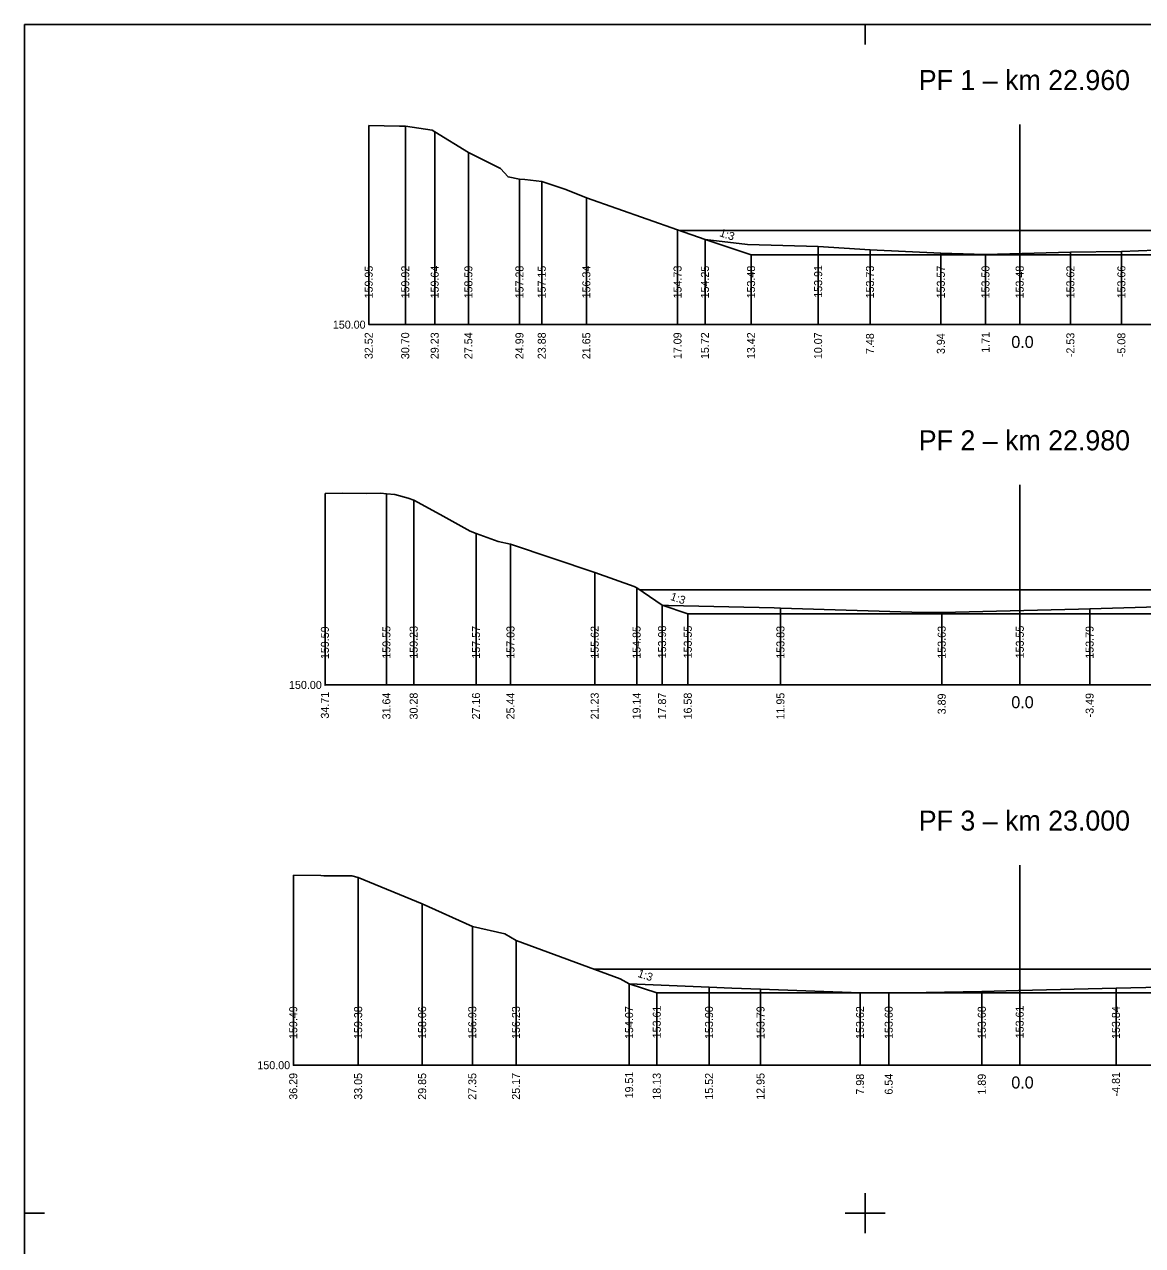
# Model space of a CAD drawing. Extents: x -582678 to -581845, y -1210354 to -1210235.
# Drawn here: x -582677.5 to -582621.6, y -1210296.3 to -1210235.3 of the extents above; entities that cross this region are included whole.
import ezdxf

# ---------------------------------------------------------------- set-up
doc = ezdxf.new("R2010")
doc.units = 0
for name, color, linetype in [('_N_osa', 7, 'Continuous'), ('_N_popis', 7, 'Continuous'), ('_N_tučná', 7, 'Continuous'), ('_rámeček', 7, 'Continuous'), ('_S_hladina', 7, 'Continuous'), ('_S_popis', 7, 'Continuous'), ('_S_popis_oprav!', 7, 'Continuous'), ('_S_tenká', 7, 'Continuous'), ('_S_velmi_tenká', 7, 'Continuous')]:
    doc.layers.add(name, color=color, linetype=linetype)

msp = doc.modelspace()

# ---------------------------------------------------------------- linework, layer by layer
at = {"layer": '_N_osa'}
for p, q in [((-582627.772, -1210240.291), (-582627.772, -1210250.291)), ((-582627.772, -1210258.291), (-582627.772, -1210268.291)), ((-582627.772, -1210277.291), (-582627.772, -1210287.291))]:
    msp.add_line(p, q, dxfattribs=at)
at = {"layer": '_N_popis'}
for points in [[(-582643.497, -1210246.043), (-582643.497, -1210250.291), (-582643.497, -1210250.291), (-582643.497, -1210250.291)], [(-582641.192, -1210246.811), (-582641.192, -1210250.291), (-582641.192, -1210250.291), (-582641.192, -1210250.291)], [(-582645.637, -1210264.313), (-582645.637, -1210268.291), (-582645.637, -1210268.291), (-582645.637, -1210268.291)], [(-582644.354, -1210264.741), (-582644.354, -1210268.291), (-582644.354, -1210268.291), (-582644.354, -1210268.291)], [(-582647.284, -1210283.221), (-582647.284, -1210287.291), (-582647.284, -1210287.291), (-582647.284, -1210287.291)], [(-582645.904, -1210283.681), (-582645.904, -1210287.291), (-582645.904, -1210287.291), (-582645.904, -1210287.291)]]:
    msp.add_lwpolyline(points, dxfattribs=at)
at = {"layer": '_N_tučná'}
for p, q in [((-582643.497, -1210246.043), (-582641.192, -1210246.811)), ((-582606.977, -1210246.811), (-582641.192, -1210246.811)), ((-582645.637, -1210264.313), (-582644.354, -1210264.741)), ((-582647.284, -1210283.221), (-582645.904, -1210283.681))]:
    msp.add_line(p, q, dxfattribs=at)
for points in [[(-582605.815, -1210264.741), (-582644.354, -1210264.741)], [(-582604.941, -1210283.681), (-582645.904, -1210283.681)]]:
    msp.add_lwpolyline(points, dxfattribs=at)
at = {"layer": '_rámeček'}
for p, q in [((-582677.502, -1210235.291), (-582677.502, -1210354.091)), ((-582467.502, -1210235.291), (-582677.502, -1210235.291)), ((-582635.502, -1210235.291), (-582635.502, -1210236.291)), ((-582635.502, -1210293.691), (-582635.502, -1210295.691)), ((-582677.502, -1210294.691), (-582676.502, -1210294.691)), ((-582636.502, -1210294.691), (-582634.502, -1210294.691))]:
    msp.add_line(p, q, dxfattribs=at)
at = {"layer": '_S_hladina'}
for points in [[(-582644.77, -1210245.591), (-582603.296, -1210245.591)], [(-582646.766, -1210263.541), (-582602.321, -1210263.541)], [(-582649.014, -1210282.501), (-582601.439, -1210282.501)]]:
    msp.add_lwpolyline(points, dxfattribs=at)
at = {"layer": '_S_tenká'}
for p, q in [((-582587.316, -1210250.291), (-582660.294, -1210250.291)), ((-582584.418, -1210268.291), (-582662.484, -1210268.291)), ((-582582.203, -1210287.291), (-582664.065, -1210287.291))]:
    msp.add_line(p, q, dxfattribs=at)
for points in [[(-582618.443, -1210246.469), (-582622.691, -1210246.633), (-582625.239, -1210246.67), (-582629.482, -1210246.788), (-582631.711, -1210246.721), (-582635.252, -1210246.559), (-582637.841, -1210246.38), (-582641.383, -1210246.287), (-582643.497, -1210246.043), (-582644.866, -1210245.557), (-582649.424, -1210243.955), (-582650.454, -1210243.546), (-582651.649, -1210243.14), (-582652.497, -1210243.04), (-582652.763, -1210243.016), (-582653.335, -1210242.907), (-582653.723, -1210242.484), (-582654.282, -1210242.199), (-582654.819, -1210241.933), (-582655.315, -1210241.697), (-582656.998, -1210240.655), (-582657.139, -1210240.581), (-582658.471, -1210240.373), (-582658.763, -1210240.373), (-582660.294, -1210240.345)], [(-582618.037, -1210264.313), (-582624.278, -1210264.498), (-582624.833, -1210264.51), (-582631.667, -1210264.665), (-582632.158, -1210264.68), (-582632.612, -1210264.674), (-582639.726, -1210264.461), (-582640.05, -1210264.448), (-582645.317, -1210264.328), (-582645.637, -1210264.313), (-582646.912, -1210263.441), (-582647.038, -1210263.37), (-582649.005, -1210262.676), (-582653.211, -1210261.258), (-582653.826, -1210261.133), (-582654.934, -1210260.722), (-582655.225, -1210260.61), (-582656.73, -1210259.779), (-582658.05, -1210259.064), (-582658.336, -1210258.954), (-582659.002, -1210258.772), (-582659.411, -1210258.741), (-582659.694, -1210258.719), (-582660.421, -1210258.734), (-582661.623, -1210258.705), (-582662.484, -1210258.726)], [(-582620.747, -1210283.397), (-582622.964, -1210283.447), (-582627.835, -1210283.554), (-582629.664, -1210283.611), (-582634.315, -1210283.692), (-582635.749, -1210283.675), (-582640.72, -1210283.497), (-582642.166, -1210283.44), (-582643.291, -1210283.386), (-582647.284, -1210283.221), (-582647.733, -1210282.97), (-582652.938, -1210281.065), (-582653.503, -1210280.731), (-582655.121, -1210280.357), (-582657.625, -1210279.228), (-582660.822, -1210277.909), (-582661.149, -1210277.838), (-582661.993, -1210277.829), (-582662.55, -1210277.823), (-582662.701, -1210277.821), (-582664.065, -1210277.803)]]:
    msp.add_lwpolyline(points, dxfattribs=at)
at = {"layer": '_S_velmi_tenká'}
for points in [[(-582660.294, -1210240.345), (-582660.294, -1210250.291), (-582660.294, -1210250.291), (-582660.294, -1210250.291)], [(-582658.471, -1210240.373), (-582658.471, -1210250.291), (-582658.471, -1210250.291), (-582658.471, -1210250.291)], [(-582656.998, -1210240.655), (-582656.998, -1210250.291), (-582656.998, -1210250.291), (-582656.998, -1210250.291)], [(-582655.315, -1210241.697), (-582655.315, -1210250.291), (-582655.315, -1210250.291), (-582655.315, -1210250.291)], [(-582652.763, -1210243.016), (-582652.763, -1210250.291), (-582652.763, -1210250.291), (-582652.763, -1210250.291)], [(-582651.649, -1210243.14), (-582651.649, -1210250.291), (-582651.649, -1210250.291), (-582651.649, -1210250.291)], [(-582649.424, -1210243.955), (-582649.424, -1210250.291), (-582649.424, -1210250.291), (-582649.424, -1210250.291)], [(-582644.866, -1210245.557), (-582644.866, -1210250.291), (-582644.866, -1210250.291), (-582644.866, -1210250.291)], [(-582637.841, -1210246.38), (-582637.841, -1210250.291), (-582637.841, -1210250.291), (-582637.841, -1210250.291)], [(-582635.252, -1210246.559), (-582635.252, -1210250.291), (-582635.252, -1210250.291), (-582635.252, -1210250.291)], [(-582625.239, -1210246.67), (-582625.239, -1210250.291), (-582625.239, -1210250.291), (-582625.239, -1210250.291)], [(-582622.691, -1210246.633), (-582622.691, -1210250.291), (-582622.691, -1210250.291), (-582622.691, -1210250.291)], [(-582631.711, -1210246.721), (-582631.711, -1210250.291), (-582631.711, -1210250.291), (-582631.711, -1210250.291)], [(-582629.482, -1210246.788), (-582629.482, -1210250.291), (-582629.482, -1210250.291), (-582629.482, -1210250.291)], [(-582662.484, -1210258.726), (-582662.484, -1210268.312), (-582662.484, -1210268.312), (-582662.484, -1210268.312)], [(-582659.411, -1210258.741), (-582659.411, -1210268.291), (-582659.411, -1210268.291), (-582659.411, -1210268.291)], [(-582658.05, -1210259.064), (-582658.05, -1210268.291), (-582658.05, -1210268.291), (-582658.05, -1210268.291)], [(-582654.934, -1210260.722), (-582654.934, -1210268.291), (-582654.934, -1210268.291), (-582654.934, -1210268.291)], [(-582653.211, -1210261.258), (-582653.211, -1210268.291), (-582653.211, -1210268.291), (-582653.211, -1210268.291)], [(-582649.005, -1210262.676), (-582649.005, -1210268.291), (-582649.005, -1210268.291), (-582649.005, -1210268.291)], [(-582646.912, -1210263.441), (-582646.912, -1210268.291), (-582646.912, -1210268.291), (-582646.912, -1210268.291)], [(-582639.726, -1210264.461), (-582639.726, -1210268.291), (-582639.726, -1210268.291), (-582639.726, -1210268.291)], [(-582631.667, -1210264.665), (-582631.667, -1210268.291), (-582631.667, -1210268.291), (-582631.667, -1210268.291)], [(-582624.278, -1210264.498), (-582624.278, -1210268.291), (-582624.278, -1210268.291), (-582624.278, -1210268.291)], [(-582664.065, -1210277.803), (-582664.065, -1210287.291), (-582664.065, -1210287.291), (-582664.065, -1210287.291)], [(-582660.822, -1210277.909), (-582660.822, -1210287.291), (-582660.822, -1210287.291), (-582660.822, -1210287.291)], [(-582657.625, -1210279.228), (-582657.625, -1210287.291), (-582657.625, -1210287.291), (-582657.625, -1210287.291)], [(-582655.121, -1210280.357), (-582655.121, -1210287.291), (-582655.121, -1210287.291), (-582655.121, -1210287.291)], [(-582652.938, -1210281.065), (-582652.938, -1210287.291), (-582652.938, -1210287.291), (-582652.938, -1210287.291)], [(-582643.291, -1210283.386), (-582643.291, -1210287.291), (-582643.291, -1210287.291), (-582643.291, -1210287.291)], [(-582640.72, -1210283.497), (-582640.72, -1210287.291), (-582640.72, -1210287.291), (-582640.72, -1210287.291)], [(-582635.749, -1210283.675), (-582635.749, -1210287.291), (-582635.749, -1210287.291), (-582635.749, -1210287.291)], [(-582634.315, -1210283.692), (-582634.315, -1210287.291), (-582634.315, -1210287.291), (-582634.315, -1210287.291)], [(-582629.664, -1210283.611), (-582629.664, -1210287.291), (-582629.664, -1210287.291), (-582629.664, -1210287.291)], [(-582622.964, -1210283.447), (-582622.964, -1210287.291), (-582622.964, -1210287.291), (-582622.964, -1210287.291)]]:
    msp.add_lwpolyline(points, dxfattribs=at)

# ---------------------------------------------------------------- texts
at = {"layer": '_N_popis'}
for s, height, rotation, p in [('1:3', 0.4, 341.56505, (-582642.808, -1210245.861)), ('154.25', 0.4, 90, (-582643.304, -1210248.982)), ('153.48', 0.4, 90, (-582640.999, -1210248.982)), ('153.48', 0.4, 90, (-582627.579, -1210248.982)), ('15.72', 0.4, 90, (-582643.304, -1210252.013)), ('13.42', 0.4, 90, (-582640.999, -1210252.013)), ('0.0', 0.6, 360, (-582628.196, -1210251.456)), ('1:3', 0.4, 341.56505, (-582645.261, -1210264.037)), ('153.98', 0.4, 90, (-582645.444, -1210266.966)), ('153.55', 0.4, 90, (-582644.16, -1210266.967)), ('153.55', 0.4, 90, (-582627.572, -1210266.967)), ('17.87', 0.4, 90, (-582645.444, -1210270.016)), ('16.58', 0.4, 90, (-582644.16, -1210270.017)), ('0.0', 0.6, 360, (-582628.196, -1210269.456)), ('1:3', 0.4, 341.56505, (-582646.894, -1210282.87)), ('154.07', 0.4, 90, (-582647.091, -1210285.981)), ('153.61', 0.4, 90, (-582645.711, -1210285.949)), ('153.61', 0.4, 90, (-582627.579, -1210285.949)), ('19.51', 0.4, 90, (-582647.091, -1210288.953)), ('18.13', 0.4, 90, (-582645.711, -1210289.016)), ('0.0', 0.6, 360, (-582628.196, -1210288.456))]:
    msp.add_text(s, height=height, rotation=rotation, dxfattribs=at).set_placement(p)
at = {"layer": '_S_popis'}
for s, p in [('159.95', (-582660.101, -1210248.982)), ('159.92', (-582658.277, -1210248.98)), ('159.64', (-582656.805, -1210248.981)), ('158.59', (-582655.121, -1210248.982)), ('157.28', (-582652.57, -1210248.982)), ('157.15', (-582651.456, -1210248.982)), ('156.34', (-582649.23, -1210248.981)), ('154.73', (-582644.673, -1210248.981)), ('153.91', (-582637.648, -1210248.949)), ('153.73', (-582635.059, -1210248.981)), ('153.57', (-582631.518, -1210248.981)), ('153.50', (-582629.289, -1210248.981)), ('153.62', (-582625.046, -1210248.98)), ('153.66', (-582622.498, -1210248.981)), ('32.52', (-582660.101, -1210252.013)), ('30.70', (-582658.277, -1210252.015)), ('29.23', (-582656.805, -1210252.016)), ('27.54', (-582655.121, -1210252.015)), ('24.99', (-582652.57, -1210252.017)), ('23.88', (-582651.456, -1210252.017)), ('21.65', (-582649.23, -1210252.019)), ('17.09', (-582644.673, -1210252.017)), ('10.07', (-582637.648, -1210252.016)), ('7.48', (-582635.059, -1210251.762)), ('3.94', (-582631.518, -1210251.76)), ('1.71', (-582629.282, -1210251.698)), ('-2.53', (-582625.046, -1210251.914)), ('-5.08', (-582622.498, -1210251.915)), ('159.59', (-582662.291, -1210267.003)), ('159.55', (-582659.217, -1210266.982)), ('159.23', (-582657.857, -1210266.981)), ('157.57', (-582654.741, -1210266.981)), ('157.03', (-582653.018, -1210266.981)), ('155.62', (-582648.811, -1210266.98)), ('154.85', (-582646.719, -1210266.982)), ('153.83', (-582639.532, -1210266.981)), ('153.63', (-582631.474, -1210266.981)), ('153.79', (-582624.085, -1210266.982)), ('34.71', (-582662.291, -1210269.974)), ('31.64', (-582659.217, -1210270.015)), ('30.28', (-582657.857, -1210270.017)), ('27.16', (-582654.741, -1210270.016)), ('25.44', (-582653.018, -1210270.015)), ('21.23', (-582648.811, -1210270.016)), ('19.14', (-582646.719, -1210270.015)), ('11.95', (-582639.532, -1210270.019)), ('3.89', (-582631.474, -1210269.762)), ('-3.49', (-582624.085, -1210269.915)), ('159.49', (-582663.872, -1210285.982)), ('159.38', (-582660.629, -1210285.982)), ('158.06', (-582657.432, -1210285.981)), ('156.93', (-582654.927, -1210285.981)), ('156.23', (-582652.745, -1210285.981)), ('153.90', (-582643.098, -1210285.981)), ('153.79', (-582640.527, -1210285.982)), ('153.62', (-582635.556, -1210285.98)), ('153.60', (-582634.122, -1210285.981)), ('153.68', (-582629.471, -1210285.982)), ('153.84', (-582622.771, -1210285.981)), ('36.29', (-582663.872, -1210289.017)), ('33.05', (-582660.629, -1210289.019)), ('29.85', (-582657.432, -1210289.019)), ('27.35', (-582654.927, -1210289.019)), ('25.17', (-582652.745, -1210289.016)), ('15.52', (-582643.098, -1210289.013)), ('12.95', (-582640.527, -1210289.019)), ('7.98', (-582635.556, -1210288.762)), ('6.54', (-582634.122, -1210288.76)), ('1.89', (-582629.471, -1210288.762)), ('-4.81', (-582622.771, -1210288.851))]:
    msp.add_text(s, height=0.4, rotation=90, dxfattribs=at).set_placement(p)
for p in [(-582662.093, -1210250.491), (-582664.283, -1210268.491), (-582665.864, -1210287.491)]:
    msp.add_text('150.00', height=0.4, dxfattribs=at).set_placement(p)
at = {"layer": '_S_popis_oprav!'}
for s, p in [('PF 1 – km 22.960', (-582632.82, -1210238.57)), ('PF 2 – km 22.980', (-582632.82, -1210256.57)), ('PF 3 – km 23.000', (-582632.82, -1210275.57))]:
    msp.add_text(s, height=1, dxfattribs=at).set_placement(p)

doc.saveas('drawing.dxf')
